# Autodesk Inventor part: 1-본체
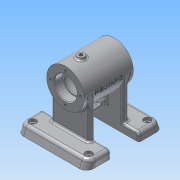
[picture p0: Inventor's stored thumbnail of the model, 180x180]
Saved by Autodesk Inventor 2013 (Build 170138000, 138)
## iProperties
Created: 2016-07
Part Number: 1-본체
Material: 알루미늄 6061
Document SubType Name: Modeling
Designer: Administrator
Density: 2.71 g/cm^3
Mass: 507.002 g
Surface Area: 536.318 cm^2
Volume: 187.086 cm^3
Author: Administrator
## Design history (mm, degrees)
sketch "스케치1"
  geometry: L1 (-35, 0)-(35, 0); L2 (-35, 16)-(-35, 27); L3 (-35, 27)-(35, 27); L4 (35, 27)-(35, 16); L5 (-21, 22)-(21, 22); L6 (-35, 16)-(-23, 16); L7 (-23, 16)-(-23, 14); L8 (21, 14)-(23, 14); L9 (23, 14)-(23, 16); L10 (23, 16)-(35, 16); L11 (-23, 14)-(-21, 14); L12 (-21, 14)-(-21, 22); L13 (21, 22)-(21, 14); 2 further points
  constraints: 26 end point, 3 perpendicular, 3 vertical, 2 vertical alignment, 1 coincident, 1 horizontal, 1 midpoint, 1 parallel
  dimensions: "d0" = 70 distance of L1.start L1.end; "d2" = 32 diameter of L6 L1; "d3" = 54 diameter of L3 L1; "d6" = 44 diameter of L5 L1; "d7" = 28 diameter of L8 L1; "d8" = 32 diameter of L10 L1; "d9" = 12 distance of L2.start L6.end; "d11" = 12 distance of L9.end L4.end; "d13" = 2 distance of L7.end L11.end; "d14" = 2 distance of L8.start L8.end; "d15" = 28 diameter of L11 L1; "d16" = 42 distance between parallel lines of L13 L12
revolve "회전1" sketch "스케치1" stored, may be unused: angle "d17" = 90 deg
node "작업 평면1"
sketch "스케치6"
  geometry: L1 (-35, 27)-(-35, -27) reference; L2 (35, 27)-(35, -27) reference; L3 (-55, -70)-(-20, -70); L4 (-20, -70)-(-20, -58); L5 (-20, -58)-(-50.632, -58); L6 (-55, -70)-(-50.632, -58); L7 (-28, -58)-(-20, -58); L8 (35, -27)-(-35, -27) reference; 4 further points
  constraints: 10 end point, 1 coincident, 1 collinear, 1 midpoint, 1 parallel, 1 perpendicular, 1 point on line
  dimensions: "d47" = 70 distance from line of L3 point (-35, 0); "d49" = 35 distance of L3.start L3.end; "d51" = 55 horizontal distance of point (0, -27) L3.start; "d52" = 12 distance between parallel lines of L3 L5; "d53" = 110 deg angle of L3 L6
extrude "돌출4" join sketch "스케치6" stored distance "d54" = 100; taper "d55" = 0 deg
node "작업 평면4"
sketch "스케치7"
  geometry: L1 (-27, 0.39)-(-27, -58); L2 (50, -58)-(-50, -58) reference; L3 (50, -70)-(50, -58) reference; L4 (-50, -70)-(50, -70) reference; L5 (-50, -58)-(-50, -70) reference; L6 (27, 0)-(27, -58); L7 (-27, -58)-(27, -58); C1 r 16 at (0, 0) reference; C2 r 27 at (0, 0) reference; 2 further points
  constraints: 6 end point, 1 horizontal alignment, 1 parallel, 1 perpendicular, 1 point on line, 1 vertical, 1 other
  dimensions: "d57" = 27 distance from line of L1 point (0, 0); "d58" = 54 distance between parallel lines of L6 L1
extrude "돌출5" join sketch "스케치7" distance "d60" = 8; taper "d61" = 0 deg
sketch "스케치8"
  geometry: L1 (-20, 0)-(-28, 0) reference; L2 (-20, -58)-(-20, 0) reference; L3 (-28, -58)-(-20, -58) reference; L4 (-28, 0)-(-28, -58) reference; L5 (28, 0)-(20, 0) reference; L6 (28, 0)-(28, -58) reference; L7 (20, -58)-(28, -58) reference; L8 (20, 0)-(20, -58) reference; L9 (20, -27)-(20, -48); L10 (20, -48)-(-20, -48); L11 (20, -70)-(55, -70) reference; L12 (35, -27)-(-35, -27) reference; L13 (-20, -48)-(-20, -27); L14 (-20, -27)-(20, -27); L15 (35, 27)-(-35, 27) reference; 3 further points
  constraints: 8 end point, 5 point on line, 1 collinear, 1 midpoint
  dimensions: "d62" = 32 distance from line of point (20, -38) L11; "d64" = 21 distance between parallel lines of L10 L12; "d65" = 35 horizontal distance of point (0, -48) L15.end
extrude "돌출6" join sketch "스케치8" stored distance "d66" = 8; taper "d67" = 0 deg
sketch "스케치9"
  geometry: L1 (20, -27)-(20, -48) reference; L2 (-8, -34.5)-(8, -34.5); L3 (8, -41.5)-(-8, -41.5); L4 (20, -70)-(55, -70) reference; L5 (-20, 0)-(-20, -58) reference; L6 (-35, -27)-(-35, 27) reference; A1 r 3.5 centre (8, -38) between (8, -41.5) and (8, -34.5); A2 r 3.5 centre (-8, -38) between (-8, -34.5) and (-8, -41.5); 3 further points
  constraints: 4 end point, 4 point on circle, 4 tangent, 2 centre point, 1 horizontal alignment, 1 midpoint, 1 parallel, 1 perpendicular, 1 vertical alignment
  dimensions: "d69" = 23 dimension on A1 A2; "d71" = 32 distance from line of L4 A1.centre; "d73" = 3.5 radius of A1; "d74" = 35 distance from line of point (0, -38) L6
extrude "돌출7" cut sketch "스케치9" distance "d75" = 8; taper "d76" = 0 deg
fillet "모깎기1" dims "d77" = 10
fillet "모깎기2" dims "d78" = 5
fillet "모깎기6" dims "d82" = 3
fillet "모깎기7" dims "d83" = 3
fillet "모깎기8" dims "d84" = 3
fillet "모깎기9" dims "d85" = 3
fillet "모깎기10" dims "d86" = 3
fillet "모깎기11" dims "d87" = 3
fillet "모깎기12" dims "d88" = 3
fillet "모깎기13" dims "d89" = 3
fillet "모깎기14" dims "d90" = 3
fillet "모깎기15" dims "d91" = 3
fillet "모깎기16" dims "d92" = 3
sketch "스케치15" dims "d122" = 42
  geometry: C1 r 16 at (0, 0) reference; C2 r 27 at (0, 0) reference; 2 further points
  constraints: 2 horizontal alignment, 1 coincident, 2 other
hole "구멍3" sketch "스케치15" at (-21, 0) diameter "d125" = 3.459; stored, may be unused: countersink angle "d129" = 90 deg, drill point angle "d131" = 118 deg; dims "d126" = 6, "d127" = 4, "d128" = 2, "d130" = 10
chamfer "모따기1" distance "d135" = 1; stored, may be unused: second distance "d136" = 2, angle "d137" = 45 deg
node "작업 평면10"
sketch "스케치18"
  geometry: L1 (35, -27)-(35, 27) reference; C1 r 5 at (13, 0); 1 further point
  constraints: 1 centre point, 1 horizontal alignment
  dimensions: "d144" = 22 distance from line of L1 C1.centre; "d145" = 10 diameter of C1
extrude "돌출10" join sketch "스케치18" distance "d146" = 4; taper "d147" = 0 deg
fillet "모깎기18" dims "d148" = 3
sketch "스케치19"
  geometry: A1 r 5 centre (13, 0) between (18, 0) and (8, 0) reference; 2 further points
  constraints: 1 coincident
hole "구멍4" sketch "스케치19" at (13, 0) diameter "d149" = 4.917; stored, may be unused: countersink angle "d153" = 90 deg, drill point angle "d155" = 118 deg; dims "d150" = 6, "d151" = 4, "d152" = 2, "d154" = 10
node "작업 평면11"
sketch "스케치20"
  geometry: L1 (-35, -27)-(-35, 27) reference; L2 (-35, 27)-(35, 27) reference; 2 further points
  constraints: 1 other
  dimensions: "d156" = 35 distance from line of point (0, 0) L1; "d157" = 27 distance from line of point (0, 0) L2
feature "엠보싱1" sketch "스케치20" dims "d158" = 0.5, "d159" = 0
sketch "스케치21"
  geometry: L1 (12.082, -19.334)-(15.898, -25.441); L2 (27, -55)-(24, -61) reference; L3 (27, -55)-(27, 0) reference; L4 (24, -12.369)-(24, -61) reference; L5 (24, -50.365)-(24.128, -50.614); L6 (10.809, -28.621)-(15.898, -25.441); L7 (6.343, -21.474)-(6.299, -21.403); L8 (12.082, -19.334)-(6.993, -22.514); L9 (10.809, -28.621)-(6.993, -22.514); A1 r 27 centre (0, 0) between (0, -27) and (24, -12.369) reference; 3 further points
  constraints: 12 end point, 3 perpendicular, 2 point on line, 1 horizontal alignment, 1 parallel, 1 vertical alignment, 1 other
  dimensions: "d160" = 30 distance of L1.end point (0, 0); "d161" = 32 deg dimension on L1.end point (0, 0) point (0, -61); "d163" = 12 diameter of L9 L1
revolve "회전3" sketch "스케치21" stored, may be unused: angle "d164" = 90 deg
sketch "스케치22"
  geometry: C1 r 6 at (0, 0) reference; 1 further point
  constraints: 1 coincident
hole "구멍5" sketch "스케치22" at (0, 0) diameter "d165" = 3; stored, may be unused: countersink angle "d169" = 90 deg, drill point angle "d171" = 118 deg; dims "d166" = 6, "d167" = 4, "d168" = 2, "d170" = 8
sketch "스케치23"
  geometry: C1 r 5 at (-5.321, 80); 4 further points; 1 other entity
  constraints: 1 centre point, 1 coincident, 1 other
  dimensions: "d172" = 10 diameter of C1
extrude "돌출11" cut sketch "스케치23" distance "d174" = 4; taper "d175" = 0 deg
sketch "스케치24"
  geometry: C1 r 5 at (0, 0) reference; C2 r 3 at (0, 0); 1 further point
  constraints: 1 centre point, 1 coincident
  dimensions: "d176" = 6 diameter of C2
extrude "돌출12" cut sketch "스케치24" stored distance "d178" = 4; taper "d179" = 0 deg
sketch "스케치25"
  geometry: C1 r 5 at (-5.321, 0); 4 further points; 1 other entity
  constraints: 1 centre point, 1 coincident, 1 other
  dimensions: "d180" = 10 diameter of C1
extrude "돌출13" cut sketch "스케치25" distance "d182" = 4; taper "d183" = 0 deg
sketch "스케치26"
  geometry: C1 r 5 at (0, 0) reference; C2 r 3 at (0, 0); 1 further point
  constraints: 1 centre point, 1 coincident
  dimensions: "d184" = 6 diameter of C2
extrude "돌출14" cut sketch "스케치26" stored distance "d186" = 4; taper "d187" = 0 deg
node "솔리드1"
mirror "대칭1"
pattern_circular "원형 패턴1" dims angle "d133" = 360 deg
mirror "대칭2"
mirror "대칭3"
node "투영된 루프4"
node "투영된 루프5"
node "투영된 루프6"
node "투영된 루프7"
node "투영된 루프8"
node "투영된 루프9"
other parameters: "d24" = 35, "d56" = 28, "d59" = 8
